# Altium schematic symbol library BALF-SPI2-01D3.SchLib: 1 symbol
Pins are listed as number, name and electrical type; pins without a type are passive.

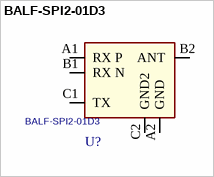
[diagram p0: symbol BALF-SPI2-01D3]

## BALF-SPI2-01D3
designator U?
footprint ST_CSP6N50x106P2x3_210x155x63
pins: A1 RX P, A2 GND, B1 RX N, B2 ANT, C1 TX, C2 GND2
